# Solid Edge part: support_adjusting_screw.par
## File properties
Title: Support adjusting screw
Author: Robert a Rhodes jr
Template: Normal.par
Last saved by: CADCIM
Revision: 13
Application: Solid Edge
Material: aluminum
Accuracy: 0.99
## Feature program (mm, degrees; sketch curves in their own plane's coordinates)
sketch for "unnamed Protrusion 1" plane through (0, 0, 0) normal (0, -1, 0) x-axis (1, 0, 0)
  circle centre (0, 0) radius 38.1
extrude "unnamed Protrusion 1" add finite 584.2 along +normal
sketch for "ExtrudedCutout_1" plane through (0, -520.7, 0) normal (0, -1, 0) x-axis (1, 0, 0)
extrude "ExtrudedCutout_1" cut finite 76.2 along +normal  Plane_Distance = 63.5 mm
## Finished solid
Body 1: solid body, 5 faces, 4 edges, 0 vertices.
  Faces by surface: plane 3, cylinder 2
  Edges by curve: circle 4
Bounding box of the edges (mm): 76.200 x 584.200 x 76.200, from (-38.1, -584.2, -38.1) to (38.1, 0, 38.1).
Cylindrical faces by radius (mm): R25.4 x1, R38.1 x1
Planar faces by outward normal: +y 1, -y 2
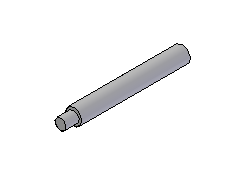
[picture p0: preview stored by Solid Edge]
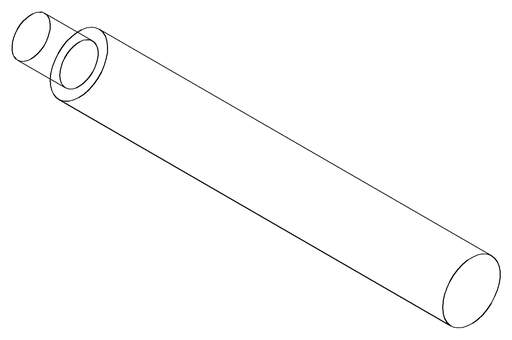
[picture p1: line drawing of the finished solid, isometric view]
